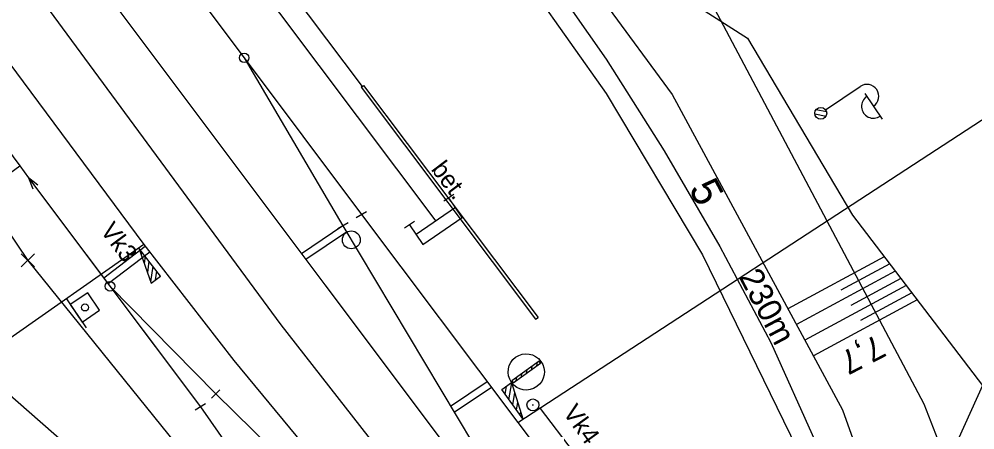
# Model space of a CAD drawing. Extents: x -804166 to -803706, y -1151030 to -1150147.
# Drawn here: x -803990.8 to -803910.7, y -1150394.2 to -1150359.8 of the extents above; entities that cross this region are included whole.
import ezdxf

# ---------------------------------------------------------------- set-up
doc = ezdxf.new("R2010")
doc.units = 0
for name, color, linetype in [('0381KM032-037P - Vrstva 1', 7, 'Continuous'), ('0381KM032-037P - Vrstva 15', 7, 'Continuous'), ('0381KM032-037P - Vrstva 16', 7, 'Continuous'), ('0381KM032-037P - Vrstva 2', 7, 'Continuous'), ('0381KM032-037P - Vrstva 25', 7, 'Continuous'), ('0381KM032-037P - Vrstva 27', 7, 'Continuous'), ('0381KM032-037P - Vrstva 3', 7, 'Continuous'), ('0381KM032-037P - Vrstva 4', 7, 'Continuous'), ('0381KM032-037P - Vrstva 48', 7, 'Continuous'), ('0381KM032-037P - Vrstva 49', 7, 'Continuous'), ('0381KM032-037P - Vrstva 51', 7, 'Continuous'), ('0381KM032-037P - Vrstva 7', 7, 'Continuous'), ('hran DP - hran DP', 7, 'Continuous'), ('PSR_C2_2_Lomove_body_Vimperk - Vrstva 60', 7, 'Continuous'), ('PSR_C2_2_trasa_Vimperk - Kabelová trasa', 7, 'Continuous')]:
    doc.layers.add(name, color=color, linetype=linetype)

msp = doc.modelspace()

# ---------------------------------------------------------------- linework, layer by layer
at = {"layer": '0381KM032-037P - Vrstva 1'}
for points in [[(-804087.926, -1150205.285), (-804078.707, -1150215.283), (-804072.371, -1150222.524), (-804072.077, -1150222.855), (-804071.467, -1150223.584), (-804065.479, -1150230.817), (-804059.467, -1150238.509), (-804055.553, -1150243.678), (-804054.356, -1150245.269), (-804043.889, -1150259.222), (-804035.374, -1150270.613), (-804034.4, -1150271.93), (-804017.97, -1150293.92), (-804002.6, -1150314.46), (-803985.38, -1150337.43), (-803955.87, -1150376.72)], [(-804090.387, -1150214.375), (-804086.648, -1150219.546), (-804073.823, -1150237.114), (-804072.555, -1150238.826), (-804064.047, -1150250.31), (-804062.807, -1150251.974), (-804052.288, -1150266.049), (-804042.5, -1150279.11), (-804026.546, -1150300.334), (-804011.272, -1150320.629), (-803993.373, -1150344.487), (-803965.171, -1150382.072), (-803953.841, -1150397.189)], [(-804093.97, -1150217.423), (-804088.165, -1150225.674), (-804077.507, -1150240.279), (-804068.519, -1150252.214), (-804067.312, -1150253.815), (-804055.014, -1150270.122), (-804046.09, -1150281.931), (-804030.046, -1150303.209), (-804014.756, -1150323.518), (-803996.92, -1150347.354), (-803968.884, -1150385.416), (-803942.597, -1150419.033)], [(-804095.554, -1150218.377), (-804090.738, -1150227.081), (-804084.011, -1150238.21), (-804078.761, -1150245.777), (-804072.115, -1150254.848), (-804070.853, -1150256.555), (-804059.975, -1150271.287), (-804049.56, -1150285.37), (-804034.127, -1150306.216), (-804018.794, -1150326.862), (-804001.176, -1150350.631), (-803980.37, -1150378.683), (-803972.82, -1150388.417), (-803965.206, -1150397.597)], [(-804088.45, -1150239.448), (-804070.362, -1150264.071), (-804054.977, -1150285.047), (-804052.95, -1150287.79), (-804037.556, -1150308.636), (-804021.871, -1150329.906), (-804004.483, -1150353.558), (-803990.764, -1150372.094)], [(-804011.14, -1150262.39), (-804005.45, -1150273.41), (-803998.73, -1150284.85), (-803991.51, -1150295.63), (-803978.8, -1150312.77), (-803963.69, -1150332.99), (-803952.21, -1150348.36), (-803946.3, -1150356.39), (-803941.6, -1150363.14), (-803936.71, -1150370.83), (-803932.05, -1150378.84), (-803927.78, -1150386.91), (-803924.06, -1150395.18), (-803920.62, -1150403.65), (-803918.06, -1150410.86), (-803915.07, -1150420.32), (-803912.96, -1150427.25), (-803910.49, -1150435.34), (-803907.334, -1150445.05), (-803903.668, -1150454.381), (-803897.938, -1150464.596), (-803891.973, -1150476.598)], [(-803981.901, -1150349.725), (-803980.965, -1150350.974), (-803971.944, -1150363.027), (-803962.118, -1150376.153)], [(-803981.901, -1150349.725), (-803980.965, -1150350.974), (-803971.944, -1150363.027), (-803963.662, -1150377.119)], [(-803990.764, -1150372.094), (-803990.029, -1150373.085), (-803975.617, -1150392.296)], [(-803990.764, -1150372.094), (-803990.029, -1150373.085), (-803983.202, -1150382.185), (-803974.334, -1150391.21)], [(-803962.118, -1150376.153), (-803948.983, -1150393.601), (-803935.254, -1150411.887)], [(-803963.662, -1150377.119), (-803952.72, -1150395.461)], [(-803974.334, -1150391.21), (-803966.535, -1150398.856)], [(-803975.617, -1150392.296), (-803939.473, -1150444.116), (-803928.265, -1150459.416), (-803914.534, -1150477.731)]]:
    msp.add_lwpolyline(points, dxfattribs=at)
at = {"layer": '0381KM032-037P - Vrstva 15'}
for p, q in [((-803954.374, -1150374.481), (-803955.199, -1150375.047)), ((-803954.221, -1150375.589), (-803957.519, -1150377.851)), ((-803957.673, -1150376.744), (-803958.497, -1150377.309))]:
    msp.add_line(p, q, dxfattribs=at)
msp.add_lwpolyline([(-803958.085, -1150377.027), (-803956.954, -1150378.676), (-803953.655, -1150376.413), (-803954.786, -1150374.764)], dxfattribs=at)
at = {"layer": '0381KM032-037P - Vrstva 16'}
for p, q in [((-803962.142, -1150365.503), (-803961.942, -1150365.353)), ((-803962.142, -1150365.503), (-803947.503, -1150384.94)), ((-803961.942, -1150365.353), (-803947.303, -1150384.79)), ((-803947.503, -1150384.94), (-803947.303, -1150384.79))]:
    msp.add_line(p, q, dxfattribs=at)
at = {"layer": '0381KM032-037P - Vrstva 2'}
for p, q in [((-803991.586, -1150372.712), (-803990.764, -1150372.094)), ((-803962.55, -1150376.405), (-803961.686, -1150375.901)), ((-803963.228, -1150376.871), (-803964.096, -1150377.367)), ((-803983.202, -1150382.185), (-803974.334, -1150391.21)), ((-803973.978, -1150390.859), (-803974.69, -1150391.561)), ((-803975.191, -1150392.034), (-803976.043, -1150392.558))]:
    msp.add_line(p, q, dxfattribs=at)
for points in [[(-803981.901, -1150349.725), (-803980.965, -1150350.974), (-803971.944, -1150363.027), (-803962.118, -1150376.153)], [(-803971.944, -1150363.027), (-803963.662, -1150377.119)], [(-803990.764, -1150372.094), (-803990.029, -1150373.085), (-803983.202, -1150382.185), (-803975.617, -1150392.296)], [(-803989.246, -1150373.707), (-803990.029, -1150373.085), (-803989.662, -1150374.015)]]:
    msp.add_lwpolyline(points, dxfattribs=at)
for centre in [(-803971.944, -1150363.027), (-803983.202, -1150382.185)]:
    msp.add_circle(centre, 0.4, dxfattribs=at)
at = {"layer": '0381KM032-037P - Vrstva 25'}
for p, q in [((-803923.18, -1150367.4), (-803920.285, -1150365.433)), ((-803919.892, -1150366.012), (-803918.431, -1150368.163)), ((-803923.983, -1150367.368), (-803923.119, -1150367.533)), ((-803924.09, -1150367.729), (-803923.149, -1150367.908))]:
    msp.add_line(p, q, dxfattribs=at)
msp.add_circle((-803923.594, -1150367.681), 0.5, dxfattribs=at)
for centre, start, end in [((-803919.723, -1150366.26), 304.19448, 124.19448), ((-803919.172, -1150367.094), 123.49191, 304.89706)]:
    msp.add_arc(centre, 1, start, end, dxfattribs=at)
at = {"layer": '0381KM032-037P - Vrstva 27'}
msp.add_line((-803947.781, -1150392.134), (-803947.681, -1150392.134), dxfattribs=at)
msp.add_circle((-803947.731, -1150392.134), 0.5, dxfattribs=at)
at = {"layer": '0381KM032-037P - Vrstva 3'}
for p, q in [((-803948.983, -1150393.601), (-803893.865, -1150357.656)), ((-803980.37, -1150378.683), (-804019.008, -1150405.813)), ((-803980.57, -1150379.244), (-803980.596, -1150379.485)), ((-803980.25, -1150379.661), (-803980.331, -1150380.274)), ((-803979.931, -1150380.078), (-803980.065, -1150381.04)), ((-803979.611, -1150380.494), (-803979.793, -1150381.825)), ((-803979.292, -1150380.911), (-803979.402, -1150381.657)), ((-803978.978, -1150381.32), (-803978.986, -1150381.338)), ((-803985.056, -1150382.728), (-803986.528, -1150383.718)), ((-803984.066, -1150384.2), (-803985.056, -1150382.728)), ((-803986.858, -1150383.228), (-803985.208, -1150385.68)), ((-803986.528, -1150383.718), (-803985.538, -1150385.19)), ((-803985.538, -1150385.19), (-803984.066, -1150384.2)), ((-803948.258, -1150389.466), (-803948.211, -1150389.176)), ((-803947.82, -1150389.151), (-803947.781, -1150388.867)), ((-803947.388, -1150388.841), (-803947.342, -1150388.551)), ((-803947.103, -1150388.636), (-803947.097, -1150388.598)), ((-803949.135, -1150390.097), (-803949.081, -1150389.802)), ((-803948.697, -1150389.782), (-803948.649, -1150389.491)), ((-803950.053, -1150391.256), (-803949.939, -1150390.552)), ((-803949.738, -1150391.694), (-803949.507, -1150390.287)), ((-803949.428, -1150392.125), (-803949.254, -1150391.102)), ((-803949.119, -1150392.556), (-803949, -1150391.917)), ((-803948.804, -1150392.994), (-803948.752, -1150392.724))]:
    msp.add_line(p, q, dxfattribs=at)
for points in [[(-803980.767, -1150378.987), (-803979.757, -1150381.929), (-803978.972, -1150381.327), (-803980.767, -1150378.987)], [(-803947.081, -1150388.62), (-803947.203, -1150388.451), (-803949.504, -1150390.106), (-803949.383, -1150390.275), (-803947.081, -1150388.62)], [(-803948.577, -1150393.309), (-803950.348, -1150390.846), (-803949.522, -1150390.252), (-803948.577, -1150393.309)]]:
    msp.add_lwpolyline(points, dxfattribs=at)
msp.add_lwpolyline([(-803947.081, -1150388.62), (-803947.203, -1150388.451), (-803949.504, -1150390.106), (-803949.383, -1150390.275)], close=True, dxfattribs=at)
msp.add_circle((-803985.295, -1150383.96), 0.296, dxfattribs=at)
msp.add_ellipse((-803948.291, -1150389.364), major_axis=(-1.233, -0.887), ratio=0.999996, dxfattribs=at)
at = {"layer": '0381KM032-037P - Vrstva 4'}
for points in [[(-804015.087, -1150257.699), (-804005.607, -1150276.645), (-803997.811, -1150289.613), (-803985.988, -1150305.967), (-803963.827, -1150335.545), (-803947.69, -1150357.387), (-803941.599, -1150366.016), (-803933.495, -1150379.543), (-803925.569, -1150395.827), (-803919.567, -1150411.363), (-803915.11, -1150425.701)], [(-804033.342, -1150270.468), (-804023.506, -1150283.74), (-804006.754, -1150306.055), (-804002.754, -1150311.23), (-803984.52, -1150335.594), (-803962.042, -1150365.446)]]:
    msp.add_lwpolyline(points, dxfattribs=at)
at = {"layer": '0381KM032-037P - Vrstva 48'}
for p, q in [((-803918.269, -1150379.708), (-803926.342, -1150384.066)), ((-803917.808, -1150380.311), (-803921.897, -1150382.519)), ((-803917.347, -1150380.915), (-803925.629, -1150385.386)), ((-803916.886, -1150381.518), (-803921.08, -1150383.782)), ((-803916.425, -1150382.122), (-803924.917, -1150386.706)), ((-803915.964, -1150382.725), (-803920.262, -1150385.046)), ((-803915.503, -1150383.329), (-803924.204, -1150388.026))]:
    msp.add_line(p, q, dxfattribs=at)
at = {"layer": '0381KM032-037P - Vrstva 49'}
msp.add_line((-803929.733, -1150361.392), (-803920.94, -1150376.21), dxfattribs=at)
for points in [[(-804010.873, -1150255.863), (-804001.608, -1150274.672), (-803994.699, -1150286.679), (-803981.461, -1150304.357), (-803936.046, -1150366.093), (-803921.768, -1150392.538), (-803912.222, -1150419.282), (-803908.812, -1150430.908)], [(-803989.471, -1150289.341), (-803982.88, -1150300.61), (-803979.03, -1150305.25), (-803971.78, -1150314.79), (-803959.62, -1150330.2), (-803952.37, -1150339.47), (-803944.88, -1150350.15), (-803937.924, -1150356.122), (-803929.733, -1150361.392)], [(-803920.94, -1150376.21), (-803910.018, -1150390.511), (-803912.553, -1150396.059), (-803903.866, -1150412.95), (-803903.684, -1150418.644), (-803901.421, -1150428.97), (-803900.537, -1150437.639), (-803895.89, -1150448.56), (-803892.01, -1150457.3), (-803887.412, -1150463.602), (-803875.883, -1150484.91), (-803874.859, -1150484.495), (-803872.322, -1150492.497), (-803872.997, -1150496.546), (-803874.041, -1150498.946)], [(-803995.514, -1150387.867), (-803978.951, -1150402.371), (-803967.974, -1150412.011), (-803952.572, -1150434.32)]]:
    msp.add_lwpolyline(points, dxfattribs=at)
at = {"layer": '0381KM032-037P - Vrstva 51'}
msp.add_line((-803947.116, -1150392.441), (-803936.561, -1150406.256), dxfattribs=at)
msp.add_lwpolyline([(-804015.087, -1150257.699), (-804005.607, -1150276.645), (-803997.811, -1150289.613), (-803985.988, -1150305.967), (-803963.827, -1150335.545), (-803947.69, -1150357.387), (-803941.599, -1150366.016), (-803933.495, -1150379.543), (-803925.569, -1150395.827), (-803919.567, -1150411.363), (-803915.11, -1150425.701)], dxfattribs=at)
at = {"layer": '0381KM032-037P - Vrstva 7'}
for p, q in [((-803963.66, -1150377.122), (-803967.136, -1150379.453)), ((-803963.353, -1150377.638), (-803966.776, -1150379.934)), ((-803980.236, -1150378.856), (-803983.711, -1150381.507)), ((-803979.868, -1150379.33), (-803983.351, -1150381.987)), ((-803951.556, -1150390.195), (-803954.63, -1150392.26)), ((-803951.195, -1150390.676), (-803954.322, -1150392.776))]:
    msp.add_line(p, q, dxfattribs=at)
msp.add_circle((-803962.962, -1150378.293), 0.75, dxfattribs=at)
at = {"layer": 'hran DP - hran DP'}
for p, q in [((-803936.41, -1150351.52), (-803914.94, -1150392.05)), ((-803914.94, -1150392.05), (-803912.08, -1150399.4))]:
    msp.add_line(p, q, dxfattribs=at)
at = {"layer": 'PSR_C2_2_Lomove_body_Vimperk - Vrstva 60'}
for p, q in [((-803990.633, -1150380.562), (-803989.533, -1150379.462)), ((-803989.533, -1150380.562), (-803990.633, -1150379.462))]:
    msp.add_line(p, q, dxfattribs=at)
at = {"layer": 'PSR_C2_2_trasa_Vimperk - Kabelová trasa'}
msp.add_lwpolyline([(-804006.069, -1150356.3), (-803990.083, -1150380.012), (-803977.679, -1150395.397)], dxfattribs=at)

# ---------------------------------------------------------------- texts
at = {"layer": '0381KM032-037P - Vrstva 1'}
for s, height, p in [('5', 2.5, (-803934.699, -1150374.008)), ('230m', 2, (-803930.503, -1150381.37))]:
    msp.add_text(s, height=height, rotation=297.88422, dxfattribs=at).set_placement(p)
at = {"layer": '0381KM032-037P - Vrstva 16'}
msp.add_text('bet.', height=1.5, rotation=306.98528, dxfattribs=at).set_placement((-803956.326, -1150372.385))
at = {"layer": '0381KM032-037P - Vrstva 3'}
for s, rotation, p in [('Vk3', 306.52798, (-803984.06, -1150377.526)), ('Vk4', 305.71645, (-803945.266, -1150392.776))]:
    msp.add_text(s, height=1.5, rotation=rotation, dxfattribs=at).set_placement(p)
at = {"layer": '0381KM032-037P - Vrstva 48'}
msp.add_text('7,7', height=2, rotation=207.3698, dxfattribs=at).set_placement((-803918.884, -1150386.177))

doc.saveas('drawing.dxf')
